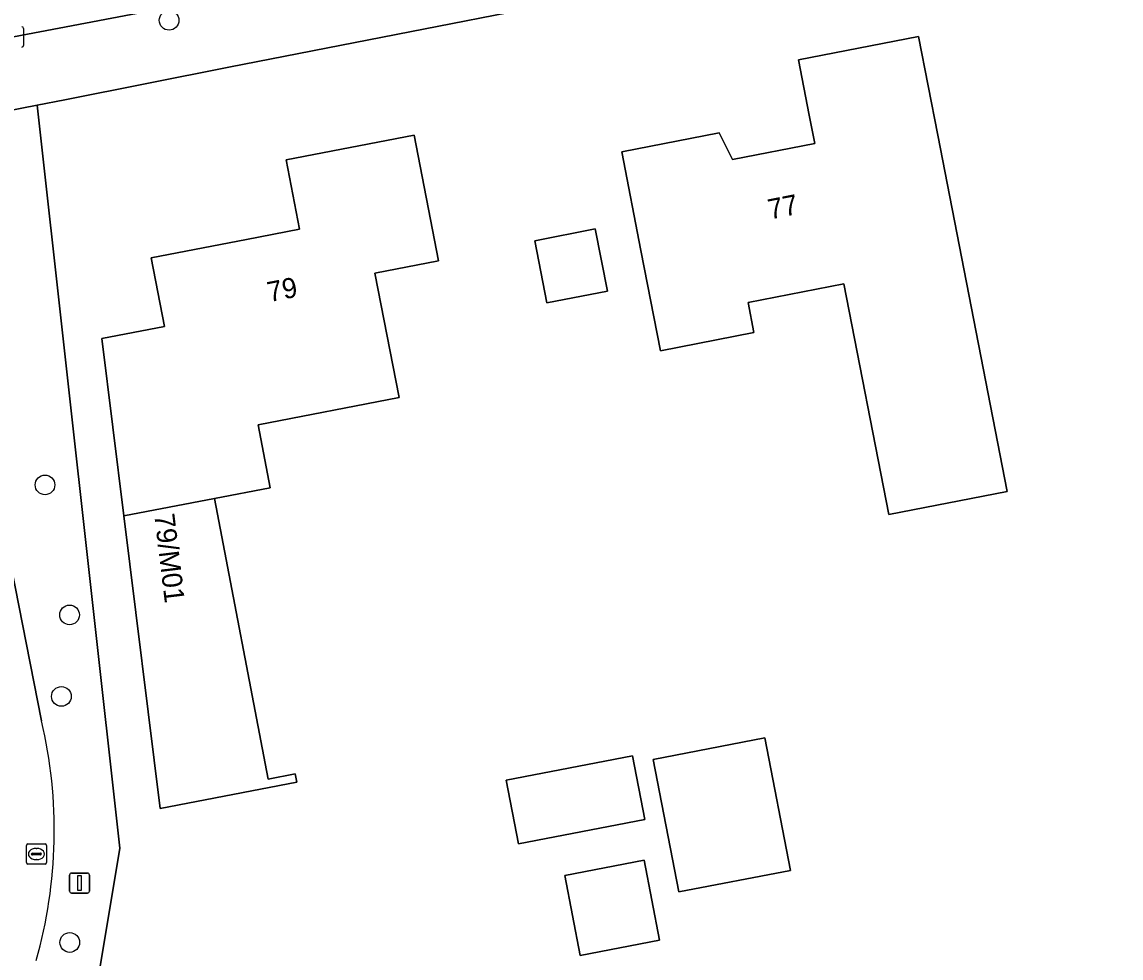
# Model space of a CAD drawing. Extents: x 157648 to 158502, y 379212 to 380938.
# Drawn here: x 158254.1 to 158308.7, y 380268.5 to 380315 of the extents above; entities that cross this region are included whole.
import ezdxf

# ---------------------------------------------------------------- set-up
doc = ezdxf.new("R2010")
doc.units = 0
for name, color, linetype in [('IMGEO_Boom', 7, 'Continuous'), ('IMGEO_Erf', 7, 'Continuous'), ('IMGEO_Groenvoorziening', 7, 'Continuous'), ('IMGEO_Kolk', 7, 'Continuous'), ('IMGEO_Lichtmast', 7, 'Continuous'), ('IMGEO_Pand', 7, 'Continuous'), ('IMGEO_Pand_nummerreeks', 7, 'Continuous'), ('IMGEO_Rijbaan_lokaal_gesloten', 7, 'Continuous'), ('IMGEO_Rioolput', 7, 'Continuous'), ('IMGEO_Voetpad_halfverhard', 7, 'Continuous'), ('IMGEO_Voetpad_open', 7, 'Continuous')]:
    doc.layers.add(name, color=color, linetype=linetype)

msp = doc.modelspace()

# ---------------------------------------------------------------- linework, layer by layer
at = {"layer": 'IMGEO_Boom'}
for centre in [(158261.404, 380315.038), (158255.234, 380291.956), (158256.455, 380285.497), (158256.048, 380281.447), (158256.467, 380269.223)]:
    msp.add_circle(centre, 0.489, dxfattribs=at)
at = {"layer": 'IMGEO_Erf'}
msp.add_lwpolyline([(158355.536, 380284.979), (158355.63, 380285.086), (158319.878, 380317.192), (158319.785, 380317.098), (158313.914, 380322.39), (158312.921, 380322.194), (158264.365, 380312.705), (158256.222, 380311.09), (158254.843, 380310.82), (158258.955, 380273.913), (158254.984, 380250), (158254.861, 380249.262), (158262.709, 380236.893), (158282.59, 380240.787), (158328.358, 380249.669)], dxfattribs=at)
for points in [[(158297.174, 380290.489), (158294.944, 380301.944), (158290.18, 380301.017), (158290.471, 380299.522), (158285.824, 380298.617), (158284.854, 380303.599), (158283.899, 380308.506), (158288.748, 380309.45), (158289.411, 380308.123), (158293.493, 380308.917), (158293.22, 380310.321), (158292.684, 380313.072), (158298.649, 380314.234), (158299.604, 380309.327), (158303.049, 380291.632)], [(158271.629, 380302.47), (158272.829, 380296.305), (158265.824, 380294.941), (158266.424, 380291.805), (158263.654, 380291.275), (158266.32, 380277.338), (158267.67, 380277.596), (158267.749, 380277.183), (158260.952, 380275.883), (158259.148, 380290.413), (158258.053, 380299.227), (158261.168, 380299.82), (158260.504, 380303.23), (158265.254, 380304.155), (158267.883, 380304.667), (158267.215, 380308.101), (158273.576, 380309.34), (158274.794, 380303.086)], [(158280.179, 380301), (158279.577, 380304.091), (158282.585, 380304.677), (158283.187, 380301.586)], [(158285.461, 380278.315), (158291.014, 380279.387), (158292.284, 380272.807), (158286.731, 380271.735)], [(158285.052, 380275.333), (158278.77, 380274.12), (158278.16, 380277.282), (158284.442, 380278.494)], [(158285.777, 380269.333), (158281.832, 380268.572), (158281.064, 380272.546), (158285.01, 380273.308)]]:
    msp.add_lwpolyline(points, close=True, dxfattribs=at)
at = {"layer": 'IMGEO_Groenvoorziening'}
for points in [[(158258.955, 380273.913), (158254.843, 380310.82), (158249.246, 380309.722), (158255.06, 380280.231)], [(158264.138, 380228.556), (158283.462, 380236.339), (158282.59, 380240.787), (158262.709, 380236.893), (158254.861, 380249.262), (158254.984, 380250), (158258.955, 380273.913)]]:
    msp.add_lwpolyline(points, dxfattribs=at)
msp.add_arc((158231.989, 380274.786), 23.705, 344.1714, 13.2795, dxfattribs=at)
at = {"layer": 'IMGEO_Kolk'}
msp.add_line((158254.163, 380314.639), (158254.163, 380313.787), dxfattribs=at)
msp.add_lwpolyline([(158254.163, 380314.639), (158254.163, 380313.787)], dxfattribs=at)
for centre, start, end in [((158254.087, 380314.637), 1.552, 88.448), ((158254.087, 380314.637), 1.552, 88.448), ((158254.087, 380313.789), 271.552, 358.448), ((158254.087, 380313.789), 271.552, 358.448)]:
    msp.add_arc(centre, 0.0765, start, end, dxfattribs=at)
at = {"layer": 'IMGEO_Lichtmast'}
for p, q in [((158256.453, 380271.774), (158256.453, 380272.574)), ((158256.453, 380272.574), (158256.453, 380271.774)), ((158256.553, 380272.674), (158257.343, 380272.674)), ((158257.343, 380272.674), (158256.553, 380272.674)), ((158257.443, 380272.574), (158257.443, 380271.774)), ((158257.443, 380271.774), (158257.443, 380272.574)), ((158257.343, 380271.674), (158256.553, 380271.674)), ((158256.553, 380271.674), (158257.343, 380271.674))]:
    msp.add_line(p, q, dxfattribs=at)
msp.add_lwpolyline([(158256.873, 380272.549), (158257.023, 380272.549), (158257.023, 380271.799), (158256.873, 380271.799), (158256.873, 380272.549)], dxfattribs=at)
for centre, start, end in [((158256.553, 380272.574), 90, 180), ((158256.553, 380272.574), 90, 180), ((158257.343, 380272.574), 0, 90), ((158257.343, 380272.574), 360, 90), ((158256.553, 380271.774), 180, 270), ((158256.553, 380271.774), 180, 270), ((158257.343, 380271.774), 270, 0), ((158257.343, 380271.774), 270, 0)]:
    msp.add_arc(centre, 0.1, start, end, dxfattribs=at)
at = {"layer": 'IMGEO_Pand'}
for points in [[(158288.748, 380309.45), (158283.899, 380308.506), (158284.854, 380303.599), (158285.824, 380298.617), (158290.471, 380299.522), (158290.18, 380301.017), (158294.944, 380301.944), (158297.174, 380290.489), (158303.049, 380291.632), (158299.604, 380309.327), (158298.649, 380314.234), (158292.684, 380313.072), (158293.22, 380310.321), (158293.493, 380308.917), (158289.411, 380308.123)], [(158271.629, 380302.47), (158274.794, 380303.086), (158273.576, 380309.34), (158267.215, 380308.101), (158267.883, 380304.667), (158265.254, 380304.155), (158260.504, 380303.23), (158261.168, 380299.82), (158258.053, 380299.227), (158259.148, 380290.413), (158263.654, 380291.275), (158266.424, 380291.805), (158265.824, 380294.941), (158272.829, 380296.305)], [(158280.179, 380301), (158283.187, 380301.586), (158282.585, 380304.677), (158279.577, 380304.091)], [(158263.654, 380291.275), (158259.148, 380290.413), (158260.952, 380275.883), (158267.749, 380277.183), (158267.67, 380277.596), (158266.32, 380277.338)], [(158285.461, 380278.315), (158286.731, 380271.735), (158292.284, 380272.807), (158291.014, 380279.387)], [(158285.052, 380275.333), (158284.442, 380278.494), (158278.16, 380277.282), (158278.77, 380274.12)], [(158281.832, 380268.572), (158285.777, 380269.333), (158285.01, 380273.308), (158281.064, 380272.546)]]:
    msp.add_lwpolyline(points, close=True, dxfattribs=at)
at = {"layer": 'IMGEO_Rijbaan_lokaal_gesloten'}
msp.add_lwpolyline([(158253.663, 380314.213), (158267.99, 380316.953)], dxfattribs=at)
at = {"layer": 'IMGEO_Rioolput'}
for p, q in [((158254.307, 380273.193), (158254.307, 380274.045)), ((158254.382, 380274.119), (158255.234, 380274.119)), ((158255.308, 380274.045), (158255.308, 380273.193)), ((158254.566, 380273.613), (158254.566, 380273.625)), ((158255.004, 380273.576), (158254.606, 380273.576)), ((158254.609, 380273.662), (158255.007, 380273.662)), ((158254.795, 380273.899), (158254.82, 380273.899)), ((158255.05, 380273.625), (158255.05, 380273.613)), ((158255.234, 380273.119), (158254.382, 380273.119)), ((158254.818, 380273.339), (158254.793, 380273.339))]:
    msp.add_line(p, q, dxfattribs=at)
for points in [[(158254.307, 380273.193), (158254.307, 380274.045)], [(158254.382, 380274.119), (158255.234, 380274.119)], [(158255.308, 380274.045), (158255.308, 380273.193)], [(158255.234, 380273.119), (158254.382, 380273.119)]]:
    msp.add_lwpolyline(points, dxfattribs=at)
for centre, radius, start, end in [((158254.384, 380274.043), 0.0765, 91.552, 178.448), ((158254.384, 380274.043), 0.0765, 91.552, 178.448), ((158255.232, 380274.043), 0.0765, 1.552, 88.448), ((158255.232, 380274.043), 0.0765, 1.552, 88.448), ((158254.606, 380273.622), 0.0403, 85.8775, 175.7526), ((158254.603, 380273.612), 0.0366, 178.938, 274.7102), ((158255.007, 380273.619), 0.043, 264.8664, 352.4533), ((158255.011, 380273.624), 0.0386, 1.7309, 96.639), ((158254.384, 380273.195), 0.0765, 181.552, 268.448), ((158254.384, 380273.195), 0.0765, 181.552, 268.448), ((158255.232, 380273.195), 0.0765, 271.552, 358.448), ((158255.232, 380273.195), 0.0765, 271.552, 358.448)]:
    msp.add_arc(centre, radius, start, end, dxfattribs=at)
for centre, major_axis, ratio, start_param, end_param in [((158254.794, 380273.619), (-0.387, 0.002), 0.722429, 4.712389, 7.853982), ((158254.819, 380273.619), (-0.39, 0.002), 0.717154, 1.570796, 4.712389)]:
    msp.add_ellipse(centre, major_axis=major_axis, ratio=ratio, start_param=start_param, end_param=end_param, dxfattribs=at)
at = {"layer": 'IMGEO_Voetpad_halfverhard'}
msp.add_lwpolyline([(158255.06, 380280.231), (158249.246, 380309.722), (158247.042, 380309.288), (158252.678, 380280.756)], dxfattribs=at)
msp.add_arc((158231.989, 380274.786), 23.705, 344.1714, 13.2795, dxfattribs=at)
at = {"layer": 'IMGEO_Voetpad_open'}
for points in [[(158241.64, 380308.242), (158247.042, 380309.288), (158249.246, 380309.722), (158254.843, 380310.82), (158256.222, 380311.09), (158264.365, 380312.705), (158312.921, 380322.194), (158313.914, 380322.39), (158316.461, 380324.918), (158315.578, 380325.699)], [(158302.731, 380323.85), (158297.03, 380322.697), (158291.127, 380321.503), (158282.495, 380319.757), (158272.265, 380317.78), (158267.99, 380316.953), (158253.663, 380314.213), (158236.263, 380310.779), (158234.715, 380310.488), (158231.813, 380309.91), (158196.789, 380303.085), (158190.936, 380301.977), (158182.046, 380300.295), (158181.583, 380300.207), (158174.809, 380298.869), (158168.769, 380297.676), (158152.391, 380294.441), (158150.782, 380294.149)]]:
    msp.add_lwpolyline(points, dxfattribs=at)

# ---------------------------------------------------------------- texts
at = {"layer": 'IMGEO_Pand_nummerreeks'}
for s, rotation, p in [('77', 11.0073, (158291.268, 380305.142)), ('79', 11.018, (158266.385, 380301.033)), ('79/M01', 276.881, (158260.661, 380290.478))]:
    msp.add_text(s, height=1, rotation=rotation, dxfattribs=at).set_placement(p)

doc.saveas('drawing.dxf')
